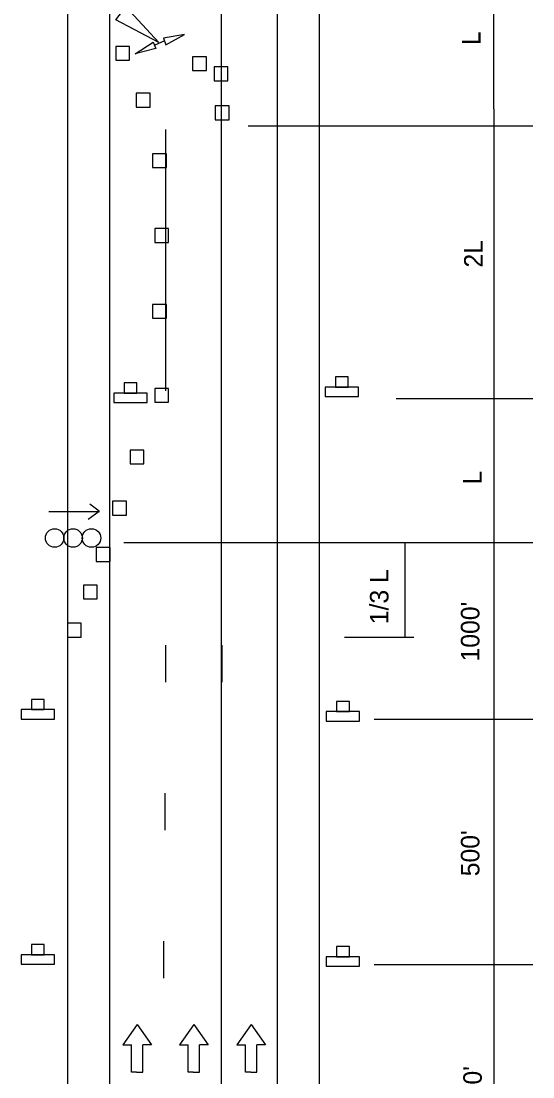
# Model space of a CAD drawing. Extents: x 1531.4 to 1538.58, y 1529.59 to 1539.33.
# Drawn here: x 1534.208 to 1535.865, y 1533.648 to 1537.071 of the extents above; entities that cross this region are included whole.
import ezdxf

# ---------------------------------------------------------------- set-up
doc = ezdxf.new("R2010")
doc.units = 0
for name, color, linetype in [('DETL-DIMS', 7, 'Continuous'), ('DETL-LINE', 7, 'Continuous'), ('DETL-NOTE', 7, 'Continuous'), ('USER-BORD', 7, 'Continuous')]:
    doc.layers.add(name, color=color, linetype=linetype)

# ---------------------------------------------------------------- blocks, each defined once
blk = doc.blocks.new('PANEL0')
at = {"layer": 'USER-BORD'}
for centre in [(0.00309, -0.00012), (0.00928, -0.00012), (0.01546, -0.00012)]:
    blk.add_circle(centre, 0.00312, dxfattribs=at)
blk = doc.blocks.new('TD')
at = {"layer": 'USER-BORD'}
for p, q in [((0, 0), (-0.0054, -0.0077)), ((0, 0), (0.0054, -0.0077)), ((-0.0054, -0.0077), (-0.0021, -0.0077)), ((-0.0021, -0.018), (-0.0021, -0.0077)), ((0.0021, -0.018), (0.0021, -0.0077)), ((0.0054, -0.0077), (0.0021, -0.0077)), ((-0.0002, -0.018), (-0.0021, -0.018)), ((-0.0002, -0.018), (0.0002, -0.018)), ((0.0002, -0.018), (0.0021, -0.018))]:
    blk.add_line(p, q, dxfattribs=at)

msp = doc.modelspace()

# ---------------------------------------------------------------- linework, layer by layer
at = {"layer": 'DETL-DIMS'}
for p, q in [((1535.739, 1536.7864), (1535.739, 1537.2326)), ((1534.6724, 1537.0069), (1534.6389, 1536.9923)), ((1535.739, 1536.7864), (1535.739, 1535.8478)), ((1534.9428, 1536.7322), (1535.8655, 1536.7322)), ((1535.423, 1535.8478), (1535.8655, 1535.8478)), ((1535.739, 1535.8478), (1535.739, 1535.3802)), ((1534.5407, 1535.3802), (1535.8655, 1535.3802)), ((1535.4505, 1535.3784), (1535.4505, 1535.0743)), ((1535.739, 1535.3802), (1535.739, 1534.8075)), ((1535.2558, 1535.0743), (1535.4798, 1535.0743)), ((1535.3511, 1534.8075), (1535.8655, 1534.8075)), ((1535.739, 1534.8075), (1535.739, 1534.0126)), ((1535.3511, 1534.0126), (1535.8655, 1534.0126)), ((1535.4342, 1534.0126), (1535.8655, 1534.0126)), ((1535.739, 1534.0126), (1535.739, 1533.1943))]:
    msp.add_line(p, q, dxfattribs=at)
for points in [[(1534.5148, 1537.0758), (1534.5467, 1537.1172), (1534.6535, 1537.0018)], [(1534.669, 1537.0164), (1534.6767, 1536.9948), (1534.737, 1537.0276)], [(1534.6354, 1537.0026), (1534.644, 1536.982), (1534.5769, 1536.9656)]]:
    msp.add_lwpolyline(points, close=True, dxfattribs=at)
at = {"layer": 'DETL-LINE'}
for p, q in [((1534.3579, 1539.0677), (1534.3579, 1532.0386)), ((1534.4942, 1539.0677), (1534.4942, 1532.8569)), ((1534.8559, 1539.0677), (1534.8559, 1532.8233)), ((1535.0367, 1539.0677), (1535.0367, 1532.8569)), ((1535.173, 1539.0677), (1535.173, 1532.0854)), ((1535.173, 1538.2844), (1535.173, 1532.2515)), ((1534.4942, 1538.2728), (1534.4942, 1532.062)), ((1534.4942, 1538.261), (1534.4942, 1532.0502)), ((1534.4942, 1538.2494), (1534.4942, 1532.0386)), ((1534.8559, 1538.261), (1534.8559, 1532.0166)), ((1535.0367, 1538.2728), (1535.0367, 1532.062)), ((1535.0367, 1538.261), (1535.0367, 1532.0502)), ((1535.0367, 1538.2494), (1535.0367, 1532.0386)), ((1535.173, 1538.2728), (1535.173, 1532.0386)), ((1534.675, 1536.7202), (1534.675, 1535.8728)), ((1534.2978, 1535.4809), (1534.4615, 1535.4809)), ((1534.4606, 1535.4809), (1534.4253, 1535.4551)), ((1534.4606, 1535.4818), (1534.4305, 1535.505))]:
    msp.add_line(p, q, dxfattribs=at)
for points in [[(1534.5142, 1536.9443), (1534.559, 1536.9443), (1534.559, 1536.9891), (1534.5142, 1536.9891)], [(1534.7634, 1536.911), (1534.8082, 1536.911), (1534.8082, 1536.9558), (1534.7634, 1536.9558)], [(1534.8331, 1536.8778), (1534.8779, 1536.8778), (1534.8779, 1536.9226), (1534.8331, 1536.9226)], [(1534.5806, 1536.7924), (1534.6254, 1536.7924), (1534.6254, 1536.8372), (1534.5806, 1536.8372)], [(1534.8365, 1536.7514), (1534.8813, 1536.7514), (1534.8813, 1536.7962), (1534.8365, 1536.7962)], [(1534.6337, 1536.5963), (1534.6785, 1536.5963), (1534.6785, 1536.6411), (1534.6337, 1536.6411)], [(1534.6404, 1536.3537), (1534.6852, 1536.3537), (1534.6852, 1536.3985), (1534.6404, 1536.3985)], [(1534.6337, 1536.1078), (1534.6785, 1536.1078), (1534.6785, 1536.1526), (1534.6337, 1536.1526)], [(1534.5415, 1535.8654), (1534.5827, 1535.8654), (1534.5827, 1535.8982), (1534.5415, 1535.8982)], [(1535.1928, 1535.8847), (1535.1928, 1535.8538), (1535.301, 1535.8538), (1535.301, 1535.8847)], [(1535.2264, 1535.8847), (1535.2677, 1535.8847), (1535.2677, 1535.9174), (1535.2264, 1535.9174)], [(1534.5079, 1535.8654), (1534.5079, 1535.8345), (1534.6161, 1535.8345), (1534.6161, 1535.8654)], [(1534.6404, 1535.8352), (1534.6852, 1535.8352), (1534.6852, 1535.88), (1534.6404, 1535.88)], [(1534.5606, 1535.6358), (1534.6054, 1535.6358), (1534.6054, 1535.6806), (1534.5606, 1535.6806)], [(1534.5041, 1535.4697), (1534.5489, 1535.4697), (1534.5489, 1535.5145), (1534.5041, 1535.5145)], [(1534.451, 1535.3193), (1534.4958, 1535.3193), (1534.4958, 1535.3641), (1534.451, 1535.3641)], [(1534.4094, 1535.198), (1534.4542, 1535.198), (1534.4542, 1535.2428), (1534.4094, 1535.2428)], [(1534.3579, 1535.074), (1534.4027, 1535.074), (1534.4027, 1535.1188), (1534.3579, 1535.1188)], [(1534.2414, 1534.8389), (1534.2827, 1534.8389), (1534.2827, 1534.8717), (1534.2414, 1534.8717)], [(1535.2298, 1534.8326), (1535.2711, 1534.8326), (1535.2711, 1534.8654), (1535.2298, 1534.8654)], [(1534.2078, 1534.8389), (1534.2078, 1534.808), (1534.316, 1534.808), (1534.316, 1534.8389)], [(1535.1962, 1534.8326), (1535.1962, 1534.8017), (1535.3044, 1534.8017), (1535.3044, 1534.8326)], [(1534.2414, 1534.044), (1534.2827, 1534.044), (1534.2827, 1534.0768), (1534.2414, 1534.0768)], [(1535.2298, 1534.0377), (1535.2711, 1534.0377), (1535.2711, 1534.0705), (1535.2298, 1534.0705)], [(1534.2078, 1534.044), (1534.2078, 1534.0131), (1534.316, 1534.0131), (1534.316, 1534.044)], [(1535.1962, 1534.0377), (1535.1962, 1534.0068), (1535.3044, 1534.0068), (1535.3044, 1534.0377)]]:
    msp.add_lwpolyline(points, close=True, dxfattribs=at)
for points in [[(1534.8559, 1536.9677), (1534.8559, 1536.8477)], [(1534.8559, 1536.4877), (1534.8559, 1536.3677)], [(1534.8559, 1536.0077), (1534.8559, 1535.8877)], [(1534.8559, 1535.5277), (1534.8559, 1535.4077)], [(1534.675, 1535.0477), (1534.675, 1534.9277)], [(1534.8577, 1535.0477), (1534.8577, 1534.9277)], [(1534.6732, 1534.5677), (1534.6732, 1534.4477)], [(1534.8559, 1534.5677), (1534.8559, 1534.4477)], [(1534.6688, 1534.0877), (1534.6688, 1533.9677)], [(1534.8559, 1534.0877), (1534.8559, 1533.9677)]]:
    msp.add_lwpolyline(points, dxfattribs=at)

# ---------------------------------------------------------------- block references
for name, p, xscale, yscale in [('PANEL0', (1534.2865, 1535.3964), 9.645601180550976, 9.645601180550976), ('TD', (1534.5836, 1533.8179), 8.611764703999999, 8.611764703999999), ('TD', (1534.7671, 1533.8179), 8.611764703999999, 8.611764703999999), ('TD', (1534.9531, 1533.8179), 8.611764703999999, 8.611764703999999)]:
    msp.add_blockref(name, p, dxfattribs=dict(at, xscale=xscale, yscale=yscale))

# ---------------------------------------------------------------- texts
at = {"layer": 'DETL-NOTE'}
for s, p in [('L', (1535.6959, 1536.9933)), ('2L', (1535.7028, 1536.2721)), ('L', (1535.6993, 1535.5689)), ('1/3 L', (1535.3977, 1535.1157)), ("1000'", (1535.6924, 1534.9949)), ("500'", (1535.6924, 1534.2985)), ("1100'", (1535.7002, 1533.4892))]:
    msp.add_text(s, height=0.06, rotation=90, dxfattribs=at).set_placement(p)

doc.saveas('drawing.dxf')
